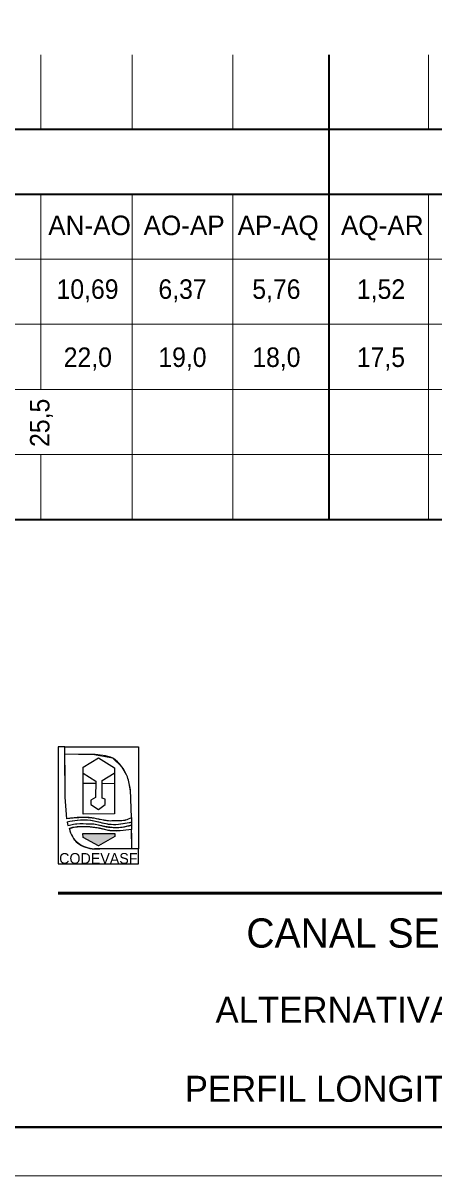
# Model space of a CAD drawing. Extents: x 8458 to 9360, y 19921 to 20366.
# Drawn here: x 9182.2 to 9245.4, y 19920.7 to 20097.9 of the extents above; entities that cross this region are included whole.
import ezdxf
from ezdxf.enums import TextEntityAlignment as Align

# ---------------------------------------------------------------- set-up
doc = ezdxf.new("R2010")
doc.units = 0
doc.header["$LTSCALE"] = 1.2
for name, color, linetype, lineweight in [('1', 7, 'Continuous', 40), ('3', 7, 'Continuous', 25), ('5', 7, 'Continuous', 13), ('8', 7, 'Continuous', 13)]:
    doc.layers.add(name, color=color, linetype=linetype, lineweight=lineweight)

msp = doc.modelspace()

# ---------------------------------------------------------------- hatches: boundary and pattern name
at = {"layer": '8'}
msp.add_hatch(color=256, dxfattribs=at).paths.add_polyline_path([(9191.38, 19973.3), (9191.4, 19972.73), (9193.77, 19971.4), (9196.31, 19972.86), (9196.31, 19973.3)])

# ---------------------------------------------------------------- linework, layer by layer
at = {"layer": '1', "lineweight": 53}
msp.add_line((9187.57, 19964.17), (9337.57, 19964.17), dxfattribs=at)
at = {"layer": '1'}
msp.add_line((8495.27, 19928.17), (9352.57, 19928.17), dxfattribs=at)
at = {"layer": '1', "lineweight": 13}
msp.add_lwpolyline([(8457.77, 19920.67), (9360.07, 19920.67), (9360.07, 20366.17), (8457.77, 20366.17)], close=True, dxfattribs=at)
at = {"layer": '3'}
for p, q in [((9188.59, 19985.51), (9188.59, 19986.62)), ((9192.85, 19985.48), (9188.59, 19985.51)), ((9191.43, 19976.31), (9191.43, 19983.52)), ((9193.36, 19981), (9191.47, 19981.02)), ((9196.2, 19980.97), (9194.32, 19980.99)), ((9198.85, 19975.79), (9198.68, 19980.01)), ((9198.9, 19971.01), (9198.85, 19973.95)), ((9199.92, 19970.95), (9193.14, 19970.95))]:
    msp.add_line(p, q, dxfattribs=at)
for points in [[(9188.59, 19986.62), (9187.57, 19986.63), (9187.57, 19968.67), (9199.94, 19968.67), (9199.92, 19970.95)], [(9188.59, 19986.63), (9199.94, 19986.63), (9199.92, 19970.95)], [(9188.88, 19975.6), (9188.65, 19978.92), (9188.59, 19985.51)], [(9191.43, 19983.52), (9193.75, 19984.96), (9196.24, 19983.43)], [(9196.24, 19983.43), (9196.24, 19976.32), (9191.43, 19976.31)], [(9191.43, 19982.6), (9193.36, 19981.35), (9193.33, 19978.88), (9192.6, 19978.45), (9192.6, 19977.76), (9193.75, 19976.99), (9194.82, 19977.78), (9194.82, 19978.62), (9194.32, 19978.74), (9194.32, 19981.47), (9196.21, 19982.61)]]:
    msp.add_lwpolyline(points, dxfattribs=at)
msp.add_lwpolyline([(9191.38, 19973.3), (9196.31, 19973.3), (9196.31, 19972.86), (9193.77, 19971.4), (9191.4, 19972.73)], close=True, dxfattribs=at)
msp.add_lwpolyline([(9191.38, 19973.3), (9196.31, 19973.3), (9196.31, 19972.86), (9193.77, 19971.4), (9191.4, 19972.73)], close=True, dxfattribs=at)
for centre, radius, start, end in [((9192.7, 19975.75), 9.73, 70.2011, 89.1197), ((9192.35, 19979.74), 6.32, 21.2511, 54.7896), ((9188.11, 19978.8), 10.63, 6.5558, 17.6915), ((9193.22, 19974.86), 4.01, 191.372, 229.2203), ((9193.28, 19975.54), 4.58, 234.1389, 268.0902)]:
    msp.add_arc(centre, radius, start, end, dxfattribs=at)
for points in [[(9198.85, 19975.72), (9197.86, 19975.35), (9196.84, 19975.26), (9196.06, 19975.25), (9195.08, 19975.26), (9193.49, 19975.59), (9191.98, 19975.79), (9190.01, 19975.72), (9188.88, 19975.6)], [(9198.85, 19975.04), (9197.56, 19974.79), (9196.09, 19974.66), (9194.57, 19974.87), (9192.59, 19975.3), (9190.5, 19975.31), (9188.97, 19975.08)], [(9189.08, 19974.55), (9189.95, 19974.75), (9191.89, 19974.83), (9193.28, 19974.75), (9194.95, 19974.37), (9196.37, 19974.24), (9197.43, 19974.3), (9198.85, 19974.59)], [(9198.85, 19973.95), (9197.13, 19973.75), (9195.66, 19973.75), (9195.12, 19973.83), (9193.56, 19974.2), (9192.06, 19974.34), (9189.96, 19974.26), (9189.29, 19974.07)]]:
    msp.add_spline(points, degree=3, dxfattribs=at)
at = {"layer": '5'}
for p, q in [((9184.9, 20093.05), (9184.9, 20081.61)), ((9198.95, 20093.05), (9198.95, 20081.61)), ((9214.44, 20093.05), (9214.44, 20081.61)), ((9244.54, 20093.05), (9244.54, 20081.61)), ((9184.9, 20071.61), (9184.9, 20041.61)), ((9198.95, 20071.61), (9198.95, 20021.61)), ((9214.44, 20071.61), (9214.44, 20021.61)), ((9244.54, 20071.61), (9244.54, 20021.61)), ((8517.12, 20061.6), (9319.97, 20061.61)), ((8517.12, 20051.6), (9319.97, 20051.61)), ((8517.12, 20041.6), (9319.97, 20041.61)), ((8535.69, 20041.6), (9319.97, 20041.61)), ((8517.12, 20031.6), (9319.97, 20031.61)), ((9184.9, 20031.61), (9184.9, 20021.61))]:
    msp.add_line(p, q, dxfattribs=at)
at = {"layer": '5', "lineweight": 35}
for p, q in [((9229.22, 20093.05), (9229.22, 20021.61)), ((8585.69, 20081.6), (9319.97, 20081.61)), ((8585.69, 20071.6), (9319.97, 20071.61)), ((8517.12, 20021.6), (9319.97, 20021.61))]:
    msp.add_line(p, q, dxfattribs=at)
at = {"layer": '8', "lineweight": 25}
msp.add_line((9188.97, 19975.08), (9189.08, 19974.55), dxfattribs=at)
at = {"layer": '8'}
for points in [[(9187.57, 19968.67), (9187.57, 19986.63), (9188.59, 19986.62), (9188.59, 19985.51), (9188.62, 19982.22), (9188.65, 19978.92), (9188.88, 19975.6), (9190.77, 19975.78), (9192.19, 19975.78), (9192.89, 19975.67), (9193.84, 19975.56), (9195.2, 19975.27), (9195.97, 19975.27), (9196.63, 19975.34), (9197.87, 19975.34), (9198.83, 19975.74), (9198.83, 19975.05), (9196.92, 19974.76), (9196.08, 19974.69), (9194.91, 19974.8), (9193.33, 19975.16), (9192.3, 19975.38), (9191.32, 19975.42), (9189.78, 19975.2), (9188.97, 19975.09), (9189.08, 19974.54), (9190.22, 19974.83), (9191.72, 19974.83), (9193.04, 19974.83), (9193.84, 19974.61), (9194.76, 19974.43), (9195.38, 19974.32), (9196.22, 19974.25), (9197.4, 19974.29), (9198.46, 19974.54), (9198.75, 19974.58), (9198.86, 19974.58), (9198.83, 19973.96), (9198.02, 19973.88), (9196.59, 19973.7), (9195.53, 19973.74), (9194.25, 19974.07), (9192.85, 19974.29), (9191.32, 19974.39), (9190.33, 19974.32), (9189.26, 19974.1), (9189.45, 19973.41), (9189.96, 19972.43), (9190.62, 19971.84), (9191.24, 19971.4), (9192.08, 19971.15), (9192.93, 19970.93), (9193.99, 19970.93), (9196.53, 19970.95), (9199.92, 19970.95), (9199.94, 19968.67)], [(9188.59, 19986.63), (9199.94, 19986.63), (9199.92, 19970.95), (9198.9, 19971.01), (9198.85, 19975.79), (9198.68, 19979.65), (9198.24, 19982.03), (9197.33, 19983.63), (9196, 19984.9), (9194.45, 19985.32), (9192.85, 19985.48), (9190.72, 19985.49), (9188.59, 19985.51)], [(9188.59, 19985.51), (9192.85, 19985.48), (9196, 19984.9), (9197.33, 19983.63), (9198.24, 19982.03), (9198.68, 19980.01), (9198.85, 19975.79), (9197.9, 19975.37), (9195.58, 19975.27), (9193.37, 19975.62), (9191.64, 19975.8), (9189.01, 19975.61), (9188.88, 19975.6), (9188.65, 19978.92), (9188.62, 19982.22)], [(9188.97, 19975.09), (9189.08, 19974.54), (9190.22, 19974.83), (9192.38, 19974.83), (9193.04, 19974.83), (9194.76, 19974.43), (9196.31, 19974.24), (9197.4, 19974.29), (9198.81, 19974.58), (9198.85, 19975.04), (9196.5, 19974.72), (9195.49, 19974.74), (9192.3, 19975.38), (9191.32, 19975.42)], [(9198.86, 19971), (9193.13, 19970.94), (9192.17, 19971.1), (9191.09, 19971.53), (9190.05, 19972.34), (9189.5, 19973.31), (9189.31, 19974.03), (9190.01, 19974.26), (9191.07, 19974.36), (9192.51, 19974.3), (9193.74, 19974.14), (9195.53, 19973.71), (9197, 19973.71), (9198.51, 19973.91), (9198.8, 19973.93)], [(9191.38, 19973.3), (9191.4, 19972.73), (9193.77, 19971.4), (9196.31, 19972.86), (9196.31, 19973.3)]]:
    msp.add_lwpolyline(points, close=True, dxfattribs=at)
for points in [[(9196.24, 19983.43), (9193.75, 19984.96), (9191.43, 19983.52), (9191.43, 19976.31)], [(9191.43, 19976.31), (9196.24, 19976.32), (9196.24, 19983.43)]]:
    msp.add_lwpolyline(points, dxfattribs=at)
at = {"layer": '8', "lineweight": 25}
msp.add_lwpolyline([(9198.85, 19975.79), (9198.85, 19975.04), (9198.85, 19974.59), (9198.85, 19973.95)], dxfattribs=at)

# ---------------------------------------------------------------- texts
at = {"layer": '1'}
for s, height, p in [('CANAL SERTÃO ALAGOANO', 4.498, (9257.47, 19955.77)), ('ALTERNATIVA  "A" (CONSOLIDADA)', 4, (9257.22, 19944.22)), ('PERFIL LONGITUDINAL ESQUEMÁTICO', 3.998, (9257.4, 19932.07))]:
    msp.add_text(s, height=height, dxfattribs=at).set_placement(p, align=Align.CENTER)
at = {"layer": '3'}
msp.add_text('CODEVASF', height=1.639, dxfattribs=at).set_placement((9187.72, 19968.67))
at = {"layer": '5'}
for s, p in [('AN-AO', (9186.04, 20065.32)), ('AO-AP', (9200.71, 20065.32)), ('AP-AQ', (9215.18, 20065.32)), ('AQ-AR', (9231.09, 20065.32))]:
    msp.add_text(s, height=3, dxfattribs=at).set_placement(p)
at = {"layer": '5', "width": 0.95}
for s, p in [('10,69', (9187.32, 20055.52)), ('6,37', (9203, 20055.52)), ('5,76', (9217.44, 20055.52)), ('1,52', (9233.54, 20055.52)), ('22,0', (9188.42, 20045.05)), ('19,0', (9202.98, 20045.05)), ('18,0', (9217.44, 20045.05)), ('17,5', (9233.52, 20045.05))]:
    msp.add_text(s, height=3, dxfattribs=at).set_placement(p)
msp.add_text('25,5', height=3, rotation=90, dxfattribs=at).set_placement((9186.23, 20032.75))

doc.saveas('drawing.dxf')
